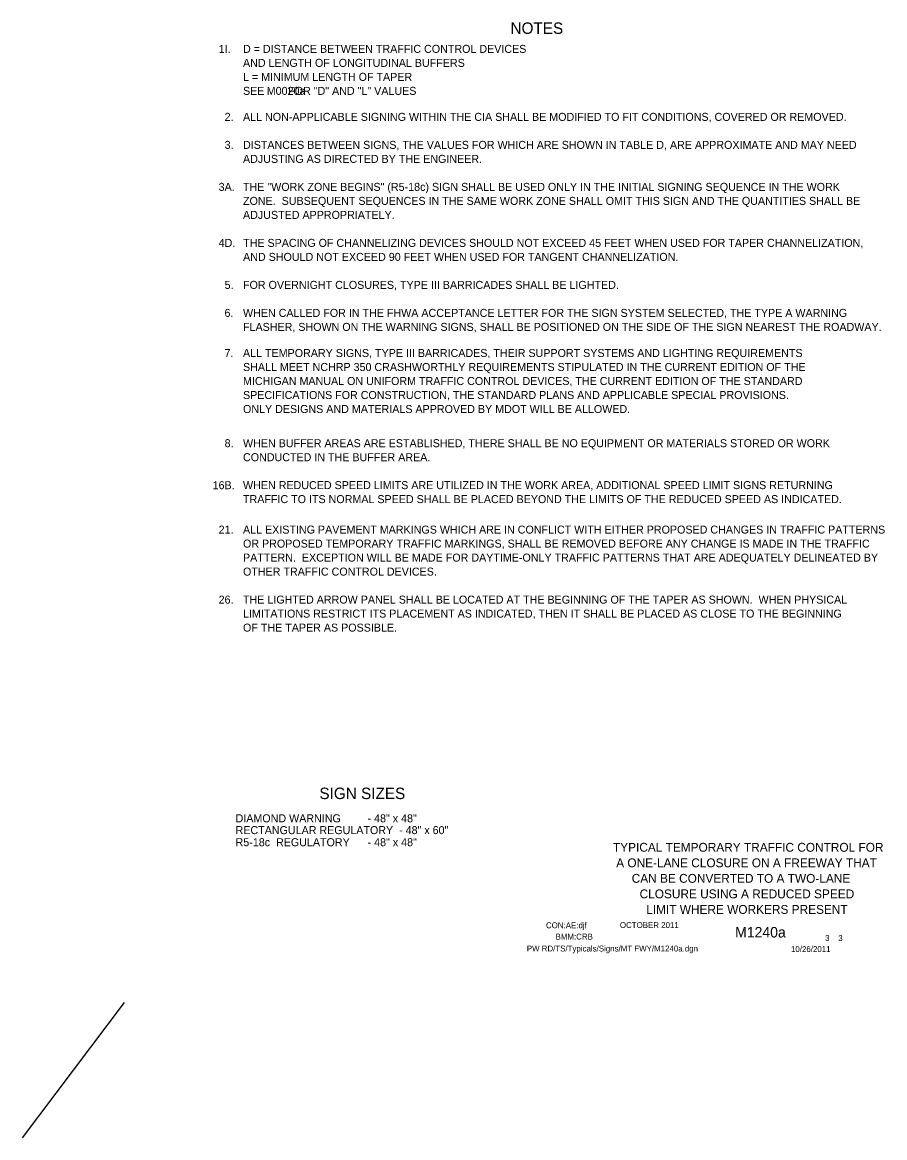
# Model space of a CAD drawing. Extents: x 16576 to 19504, y 5728 to 6974.
# Drawn here: x 18599 to 19504, y 5738 to 6909 of the extents above; entities that cross this region are included whole.
import ezdxf

# ---------------------------------------------------------------- set-up
doc = ezdxf.new("R2010")
doc.units = 0
for name, color, linetype in [('BORDER', 7, 'Continuous'), ('BORDER_SIGNAL_WO', 7, 'Continuous'), ('TYPICAL_TEXT_DIMEN_PR', 7, 'Continuous')]:
    doc.layers.add(name, color=color, linetype=linetype)

msp = doc.modelspace()

# ---------------------------------------------------------------- linework, layer by layer
at = {"layer": 'TYPICAL_TEXT_DIMEN_PR'}
msp.add_line((18705.8, 5880), (18599, 5738.2), dxfattribs=at)

# ---------------------------------------------------------------- texts
at = {"layer": 'BORDER'}
for s, p in [('TYPICAL TEMPORARY TRAFFIC CONTROL FOR', (19219, 6038.4)), ('A ONE-LANE CLOSURE ON A FREEWAY THAT', (19222.4, 6022.1)), ('CAN BE CONVERTED TO A TWO-LANE ', (19238.7, 6005.8)), ('CLOSURE USING A REDUCED SPEED', (19247, 5989.5)), ('LIMIT WHERE WORKERS PRESENT', (19253.9, 5973.2))]:
    msp.add_text(s, height=9.3, dxfattribs=at).set_placement(p)
at = {"layer": 'BORDER_SIGNAL_WO'}
for s, height, p in [('CON:AE:djf  ', 6.2, (19148.7, 5958.1)), ('    OCTOBER 2011    ', 6.2, (19217.1, 5958.3)), ('BMM:CRB   ', 6.2, (19158.8, 5946.2)), ('    M1240a   ', 11, (19330.9, 5948.4)), (' 3    3 ', 6.2, (19439.4, 5944.7)), ('PW RD/TS/Typicals/Signs/MT FWY/M1240a.dgn      ', 6.2, (19128.6, 5933.7)), ('10/26/2011    ', 6.2, (19405.9, 5933.1))]:
    msp.add_text(s, height=height, dxfattribs=at).set_placement(p)
at = {"layer": 'TYPICAL_TEXT_DIMEN_PR'}
for s, height, p in [('NOTES', 12, (19111.5, 6897)), ('1I.', 8.4, (18805.2, 6877.1)), ('D = DISTANCE BETWEEN TRAFFIC CONTROL DEVICES', 8.4, (18830.7, 6877.1)), ('AND LENGTH OF LONGITUDINAL BUFFERS', 8.4, (18830.7, 6862.4)), ('L = MINIMUM LENGTH OF TAPER', 8.4, (18830.7, 6847.7)), ('SEE        FOR "D" AND "L" VALUES', 8.4, (18830.7, 6833)), ('M0020a', 8.4, (18855.6, 6833)), ('2.', 8.4, (18811.4, 6805.7)), ('ALL NON-APPLICABLE SIGNING WITHIN THE CIA SHALL BE MODIFIED TO FIT CONDITIONS, COVERED OR REMOVED.', 8.4, (18830.7, 6805.7)), ('3.', 8.4, (18811.4, 6776.3)), ('DISTANCES BETWEEN SIGNS, THE VALUES FOR WHICH ARE SHOWN IN TABLE D, ARE APPROXIMATE AND MAY NEED', 8.4, (18830.7, 6776.3)), ('ADJUSTING AS DIRECTED BY THE ENGINEER.', 8.4, (18830.7, 6761.6)), ('3A.', 8.4, (18805.1, 6732.2)), ('THE "WORK ZONE BEGINS" (R5-18c) SIGN SHALL BE USED ONLY IN THE INITIAL SIGNING SEQUENCE IN THE WORK', 8.4, (18830.7, 6732.2)), ('ZONE.  SUBSEQUENT SEQUENCES IN THE SAME WORK ZONE SHALL OMIT THIS SIGN AND THE QUANTITIES SHALL BE', 8.4, (18830.7, 6717.5)), ('ADJUSTED APPROPRIATELY.', 8.4, (18830.7, 6702.8)), ('4D.', 8.4, (18805.1, 6673.4)), ('THE SPACING OF CHANNELIZING DEVICES SHOULD NOT EXCEED 45 FEET WHEN USED FOR TAPER CHANNELIZATION,', 8.4, (18830.8, 6673.4)), ('AND SHOULD NOT EXCEED 90 FEET WHEN USED FOR TANGENT CHANNELIZATION.', 8.4, (18830.8, 6658.7)), ('5.', 8.4, (18811.4, 6629.3)), ('FOR OVERNIGHT CLOSURES, TYPE III BARRICADES SHALL BE LIGHTED.', 8.4, (18830.7, 6629.3)), ('6.', 8.4, (18811.3, 6599.9)), ('WHEN CALLED FOR IN THE FHWA ACCEPTANCE LETTER FOR THE SIGN SYSTEM SELECTED, THE TYPE A WARNING ', 8.4, (18830.7, 6599.9)), ('FLASHER, SHOWN ON THE WARNING SIGNS, SHALL BE POSITIONED ON THE SIDE OF THE SIGN NEAREST THE ROADWAY.', 8.4, (18830.7, 6585.2)), ('7.', 8.4, (18811.3, 6557.8)), ('ALL TEMPORARY SIGNS, TYPE III BARRICADES, THEIR SUPPORT SYSTEMS AND LIGHTING REQUIREMENTS', 8.4, (18830.7, 6557.8)), ('SHALL MEET NCHRP 350 CRASHWORTHLY REQUIREMENTS STIPULATED IN THE CURRENT EDITION OF THE', 8.4, (18830.7, 6543.1)), ('MICHIGAN MANUAL ON UNIFORM TRAFFIC CONTROL DEVICES, THE CURRENT EDITION OF THE STANDARD', 8.4, (18830.7, 6528.4)), ('SPECIFICATIONS FOR CONSTRUCTION, THE STANDARD PLANS AND APPLICABLE SPECIAL PROVISIONS.', 8.4, (18830.7, 6513.7)), ('ONLY DESIGNS AND MATERIALS APPROVED BY MDOT WILL BE ALLOWED.', 8.4, (18830.7, 6499)), ('8.', 8.4, (18811.4, 6463.1)), ('WHEN BUFFER AREAS ARE ESTABLISHED, THERE SHALL BE NO EQUIPMENT OR MATERIALS STORED OR WORK     ', 8.4, (18830.7, 6463.1)), ('CONDUCTED IN THE BUFFER AREA.', 8.4, (18830.7, 6448.4)), ('16B.', 8.4, (18798.8, 6419)), ('WHEN REDUCED SPEED LIMITS ARE UTILIZED IN THE WORK AREA, ADDITIONAL SPEED LIMIT SIGNS RETURNING', 8.4, (18830.7, 6419.1)), ('TRAFFIC TO ITS NORMAL SPEED SHALL BE PLACED BEYOND THE LIMITS OF THE REDUCED SPEED AS INDICATED.', 8.4, (18830.7, 6404.4)), ('21.', 8.4, (18805.1, 6372.4)), ('ALL EXISTING PAVEMENT MARKINGS WHICH ARE IN CONFLICT WITH EITHER PROPOSED CHANGES IN TRAFFIC PATTERNS', 8.4, (18830.7, 6372.4)), ('OR PROPOSED TEMPORARY TRAFFIC MARKINGS, SHALL BE REMOVED BEFORE ANY CHANGE IS MADE IN THE TRAFFIC', 8.4, (18830.7, 6357.7)), ('PATTERN.  EXCEPTION WILL BE MADE FOR DAYTIME-ONLY TRAFFIC PATTERNS THAT ARE ADEQUATELY DELINEATED BY', 8.4, (18830.7, 6343)), ('OTHER TRAFFIC CONTROL DEVICES.', 8.4, (18830.7, 6328.3)), ('26.', 8.4, (18805.1, 6298.9)), ('THE LIGHTED ARROW PANEL SHALL BE LOCATED AT THE BEGINNING OF THE TAPER AS SHOWN.  WHEN PHYSICAL', 8.4, (18830.7, 6298.9)), ('LIMITATIONS RESTRICT ITS PLACEMENT AS INDICATED, THEN IT SHALL BE PLACED AS CLOSE TO THE BEGINNING', 8.4, (18830.7, 6284.2)), ('OF THE TAPER AS POSSIBLE.', 8.4, (18830.7, 6269.5)), ('SIGN SIZES', 12, (18910.9, 6093.7)), ('DIAMOND WARNING         - 48" x 48"', 8.4, (18822.9, 6069.3)), ('RECTANGULAR REGULATORY  - 48" x 60"', 8.4, (18822.9, 6056.9)), ('R5-18c  REGULATORY      - 48" x 48"', 8.4, (18822.9, 6044.2))]:
    msp.add_text(s, height=height, dxfattribs=at).set_placement(p)

doc.saveas('drawing.dxf')
